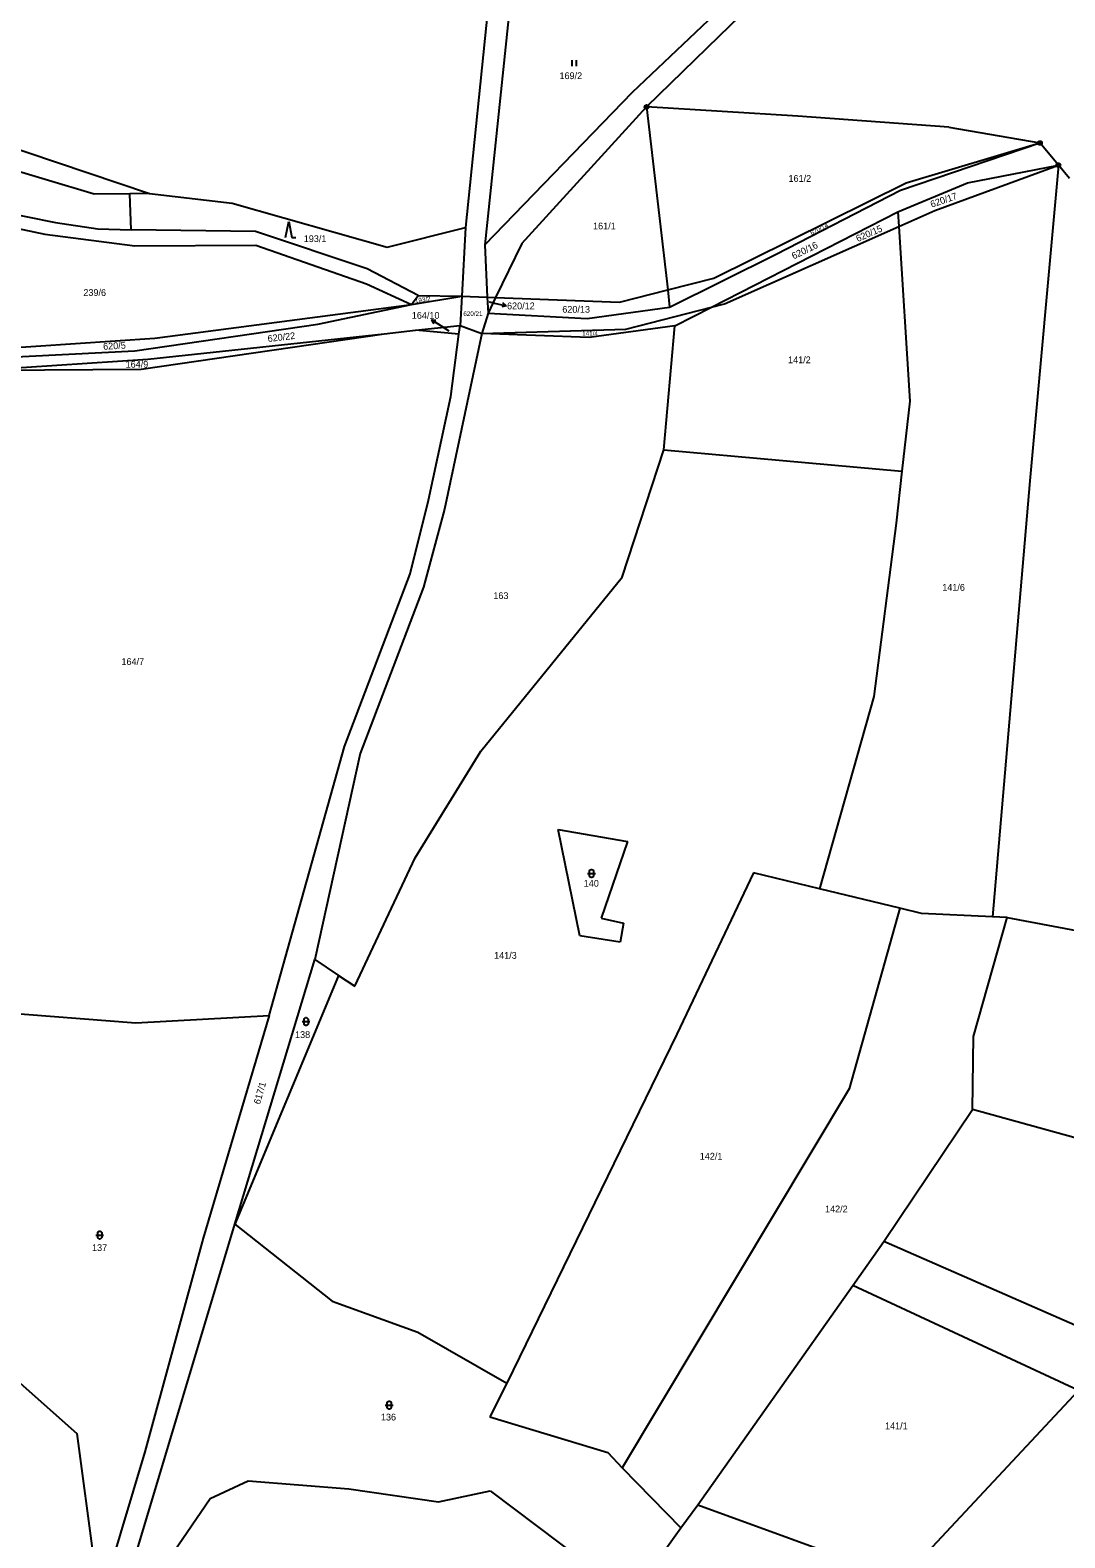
# Model space of a CAD drawing. Extents: x -794421 to -792735, y -1117671 to -1115559.
# Drawn here: x -793585 to -793325.1, y -1116417 to -1116038.2 of the extents above; entities that cross this region are included whole.
import ezdxf

# ---------------------------------------------------------------- set-up
doc = ezdxf.new("R2010")
doc.units = 0
for name, color, linetype in [('Komunikace', 7, 'Continuous'), ('Vrstva 1', 7, 'Continuous'), ('Vrstva 14', 7, 'Continuous'), ('Vrstva 16', 7, 'Continuous'), ('Vrstva 23', 7, 'Continuous'), ('Vrstva 28', 7, 'Continuous'), ('Vrstva 3', 7, 'Continuous')]:
    doc.layers.add(name, color=color, linetype=linetype)

msp = doc.modelspace()

# ---------------------------------------------------------------- linework, layer by layer
at = {"layer": 'Komunikace'}
for p, q in [((-793469.61, -1116106.43), (-793468.29, -1116106.74)), ((-793479.71, -1116113.76), (-793481.61, -1116112.55))]:
    msp.add_line(p, q, dxfattribs=at)
at = {"layer": 'Vrstva 1'}
for p, q in [((-793433.69, -1116053.72), (-793400.57, -1116022.38)), ((-793469.1, -1116023.94), (-793475.64, -1116087.76)), ((-793463.7, -1116024.71), (-793470.75, -1116092.14)), ((-793470.75, -1116092.14), (-793433.69, -1116053.72)), ((-793568.92, -1116079.35), (-793646.63, -1116056.03)), ((-793461.5, -1116091.79), (-793430.11, -1116057.44)), ((-793430.11, -1116057.44), (-793424.76, -1116103.43)), ((-793595.03, -1116065.71), (-793554.97, -1116079.2)), ((-793366.33, -1116078.39), (-793331.31, -1116066.51)), ((-793364.89, -1116076.52), (-793331.31, -1116066.51)), ((-793357.74, -1116083.48), (-793326.69, -1116072.07)), ((-793349.53, -1116076.5), (-793326.69, -1116072.07)), ((-793326.69, -1116072.07), (-793333.84, -1116151.37)), ((-793413.2, -1116100.5), (-793364.89, -1116076.52)), ((-793366.98, -1116083.8), (-793349.53, -1116076.5)), ((-793615.17, -1116079.08), (-793578.57, -1116086.49)), ((-793559.94, -1116079.27), (-793568.92, -1116079.35)), ((-793554.97, -1116079.2), (-793559.94, -1116079.27)), ((-793559.63, -1116088.36), (-793559.94, -1116079.27)), ((-793554.97, -1116079.2), (-793534.21, -1116081.67)), ((-793397.61, -1116094.45), (-793366.33, -1116078.39)), ((-793613.99, -1116082.51), (-793581.25, -1116089.41)), ((-793534.21, -1116081.67), (-793495.28, -1116092.65)), ((-793413.81, -1116107.74), (-793366.98, -1116083.8)), ((-793366.98, -1116083.8), (-793366.75, -1116087.48)), ((-793366.75, -1116087.48), (-793357.74, -1116083.48)), ((-793578.57, -1116086.49), (-793568, -1116088.05)), ((-793568, -1116088.05), (-793559.63, -1116088.36)), ((-793495.28, -1116092.65), (-793475.64, -1116087.76)), ((-793475.64, -1116087.76), (-793476.53, -1116104.96)), ((-793410.52, -1116106.9), (-793366.75, -1116087.48)), ((-793366.75, -1116087.48), (-793364.02, -1116131.35)), ((-793581.25, -1116089.41), (-793558.68, -1116092.31)), ((-793528.33, -1116088.78), (-793559.63, -1116088.36)), ((-793500.35, -1116098.15), (-793528.33, -1116088.78)), ((-793461.5, -1116091.79), (-793468.04, -1116105.33)), ((-793558.68, -1116092.31), (-793528.25, -1116092.21)), ((-793528.25, -1116092.21), (-793500.47, -1116101.91)), ((-793470.75, -1116092.14), (-793470.14, -1116105.25)), ((-793424.33, -1116107.79), (-793397.61, -1116094.45)), ((-793487.53, -1116104.85), (-793500.35, -1116098.15)), ((-793500.47, -1116101.91), (-793489.16, -1116107.13)), ((-793436.94, -1116106.52), (-793424.76, -1116103.43)), ((-793424.76, -1116103.43), (-793413.2, -1116100.5)), ((-793424.76, -1116103.43), (-793424.33, -1116107.79)), ((-793553.62, -1116115.56), (-793489.16, -1116107.13)), ((-793512.73, -1116112.02), (-793489.16, -1116107.13)), ((-793489.16, -1116107.13), (-793487.53, -1116104.85)), ((-793489.16, -1116107.13), (-793476.53, -1116104.96)), ((-793487.53, -1116104.85), (-793476.53, -1116104.96)), ((-793476.53, -1116104.96), (-793476.99, -1116112.38)), ((-793476.53, -1116104.96), (-793470.14, -1116105.25)), ((-793470.14, -1116105.25), (-793468.04, -1116105.33)), ((-793470.14, -1116105.25), (-793469.95, -1116109.28)), ((-793468.04, -1116105.33), (-793469.95, -1116109.28)), ((-793468.04, -1116105.33), (-793436.94, -1116106.52)), ((-793413.81, -1116107.74), (-793410.52, -1116106.9)), ((-793469.95, -1116109.28), (-793471.48, -1116114.35)), ((-793469.95, -1116109.28), (-793445.03, -1116110.62)), ((-793445.03, -1116110.62), (-793424.33, -1116107.79)), ((-793435.38, -1116113.28), (-793413.81, -1116107.74)), ((-793423.05, -1116112.47), (-793413.81, -1116107.74)), ((-793558.72, -1116118.73), (-793512.73, -1116112.02)), ((-793557.09, -1116123.33), (-793496.03, -1116114.43)), ((-793555.45, -1116120.83), (-793496.03, -1116114.43)), ((-793496.03, -1116114.43), (-793488.16, -1116113.58)), ((-793488.16, -1116113.58), (-793476.99, -1116112.38)), ((-793477.27, -1116114.55), (-793488.16, -1116113.58)), ((-793471.48, -1116114.35), (-793480.93, -1116158.56)), ((-793479.3, -1116130.2), (-793477.27, -1116114.55)), ((-793477.27, -1116114.55), (-793476.99, -1116112.38)), ((-793476.99, -1116112.38), (-793471.48, -1116114.35)), ((-793471.48, -1116114.35), (-793435.38, -1116113.28)), ((-793444.53, -1116115.36), (-793471.48, -1116114.35)), ((-793423.05, -1116112.47), (-793444.53, -1116115.36)), ((-793425.78, -1116143.59), (-793423.05, -1116112.47)), ((-793600.44, -1116118.71), (-793553.62, -1116115.56)), ((-793603.53, -1116120.99), (-793558.72, -1116118.73)), ((-793597.29, -1116123.63), (-793555.45, -1116120.83)), ((-793597.29, -1116123.63), (-793557.09, -1116123.33)), ((-793484.91, -1116156.22), (-793479.3, -1116130.2)), ((-793364.02, -1116131.35), (-793365.98, -1116148.93)), ((-793436.22, -1116175.62), (-793425.78, -1116143.59)), ((-793425.78, -1116143.59), (-793365.98, -1116148.93)), ((-793365.98, -1116148.93), (-793367.45, -1116162.05)), ((-793333.84, -1116151.37), (-793343.2, -1116260.98)), ((-793489.55, -1116174.74), (-793484.91, -1116156.22)), ((-793480.93, -1116158.56), (-793486.18, -1116178.14)), ((-793367.45, -1116162.05), (-793373.03, -1116205.62)), ((-793505.97, -1116218.12), (-793489.55, -1116174.74)), ((-793486.18, -1116178.14), (-793502.11, -1116219.92)), ((-793471.77, -1116219.34), (-793436.22, -1116175.62)), ((-793373.03, -1116205.62), (-793386.68, -1116253.93)), ((-793524.92, -1116285.78), (-793505.97, -1116218.12)), ((-793502.11, -1116219.92), (-793513.48, -1116271.65)), ((-793488.28, -1116246.1), (-793471.77, -1116219.34)), ((-793452.32, -1116239.04), (-793434.89, -1116242)), ((-793446.91, -1116265.75), (-793452.32, -1116239.04)), ((-793434.89, -1116242), (-793441.5, -1116261.28)), ((-793503.4, -1116278.4), (-793488.28, -1116246.1)), ((-793403.27, -1116249.91), (-793422.49, -1116290.4)), ((-793386.68, -1116253.93), (-793403.27, -1116249.91)), ((-793366.47, -1116258.82), (-793386.68, -1116253.93)), ((-793441.5, -1116261.28), (-793435.89, -1116262.54)), ((-793435.89, -1116262.54), (-793436.77, -1116267.32)), ((-793366.47, -1116258.82), (-793379.21, -1116304.19)), ((-793361.08, -1116260.12), (-793366.47, -1116258.82)), ((-793343.2, -1116260.98), (-793361.08, -1116260.12)), ((-793347.97, -1116291.05), (-793339.57, -1116261.15)), ((-793339.57, -1116261.15), (-793343.2, -1116260.98)), ((-793339.57, -1116261.15), (-793306.78, -1116267.35)), ((-793436.77, -1116267.32), (-793446.91, -1116265.75)), ((-793533.59, -1116338.16), (-793513.48, -1116271.65)), ((-793513.48, -1116271.65), (-793507.5, -1116275.68)), ((-793507.5, -1116275.68), (-793533.59, -1116338.16)), ((-793507.5, -1116275.68), (-793503.4, -1116278.4)), ((-793592.97, -1116284.93), (-793558.4, -1116287.58)), ((-793558.4, -1116287.58), (-793524.92, -1116285.78)), ((-793524.92, -1116285.78), (-793541.48, -1116341.68)), ((-793422.49, -1116290.4), (-793465.23, -1116378.1)), ((-793348.29, -1116309.37), (-793347.97, -1116291.05)), ((-793379.21, -1116304.19), (-793436.23, -1116399.41)), ((-793370.56, -1116342.5), (-793348.29, -1116309.37)), ((-793302.6, -1116322.05), (-793348.29, -1116309.37)), ((-793565.49, -1116444.67), (-793533.59, -1116338.16)), ((-793533.59, -1116338.16), (-793509.11, -1116357.56)), ((-793541.48, -1116341.68), (-793556.19, -1116395.36)), ((-793378.31, -1116353.61), (-793370.56, -1116342.5)), ((-793306.98, -1116370.42), (-793370.56, -1116342.5)), ((-793417.29, -1116408.69), (-793378.31, -1116353.61)), ((-793321.66, -1116379.99), (-793378.31, -1116353.61)), ((-793509.11, -1116357.56), (-793487.59, -1116365.35)), ((-793599.56, -1116367.45), (-793573.29, -1116390.8)), ((-793487.59, -1116365.35), (-793465.23, -1116378.1)), ((-793465.23, -1116378.1), (-793469.48, -1116386.59)), ((-793365.92, -1116427.35), (-793321.66, -1116379.99)), ((-793469.48, -1116386.59), (-793439.86, -1116395.6)), ((-793573.29, -1116390.8), (-793568.98, -1116422.79)), ((-793556.19, -1116395.36), (-793576.18, -1116462.41)), ((-793439.86, -1116395.6), (-793436.23, -1116399.41)), ((-793539.73, -1116407.1), (-793530.22, -1116402.67)), ((-793530.22, -1116402.67), (-793504.91, -1116404.65)), ((-793436.23, -1116399.41), (-793421.51, -1116414.45)), ((-793504.91, -1116404.65), (-793482.38, -1116407.93)), ((-793482.38, -1116407.93), (-793469.39, -1116405.2)), ((-793469.39, -1116405.2), (-793445.99, -1116422.87)), ((-793565.49, -1116444.67), (-793539.73, -1116407.1)), ((-793421.51, -1116414.45), (-793417.29, -1116408.69)), ((-793417.29, -1116408.69), (-793365.92, -1116427.35)), ((-793431.01, -1116427.69), (-793421.51, -1116414.45))]:
    msp.add_line(p, q, dxfattribs=at)
at = {"layer": 'Vrstva 16'}
for p, q in [((-793468.29, -1116106.74), (-793465.368, -1116107.422)), ((-793465.368, -1116107.422), (-793466.228, -1116106.707)), ((-793481.61, -1116112.55), (-793484.14, -1116110.939)), ((-793484.14, -1116110.939), (-793483.565, -1116111.897)), ((-793484.14, -1116110.939), (-793483.028, -1116111.054)), ((-793465.368, -1116107.422), (-793466.456, -1116107.681))]:
    msp.add_line(p, q, dxfattribs=at)
at = {"layer": 'Vrstva 23'}
for p, q in [((-793448.78, -1116047.23), (-793448.78, -1116045.73)), ((-793447.78, -1116045.73), (-793447.78, -1116047.23)), ((-793520.83, -1116090.24), (-793520.03, -1116086.24)), ((-793520.03, -1116086.24), (-793519.23, -1116090.24)), ((-793519.23, -1116090.24), (-793518.23, -1116090.24)), ((-793444.96, -1116250.05), (-793442.96, -1116250.05)), ((-793444.46, -1116249.45), (-793444.36, -1116249.25)), ((-793444.46, -1116250.65), (-793444.46, -1116249.45)), ((-793444.36, -1116250.85), (-793444.46, -1116250.65)), ((-793444.36, -1116249.25), (-793444.26, -1116249.15)), ((-793444.26, -1116250.95), (-793444.36, -1116250.85)), ((-793444.26, -1116249.15), (-793444.06, -1116249.05)), ((-793444.06, -1116251.05), (-793444.26, -1116250.95)), ((-793444.06, -1116249.05), (-793443.86, -1116249.05)), ((-793443.86, -1116251.05), (-793444.06, -1116251.05)), ((-793443.86, -1116249.05), (-793443.66, -1116249.15)), ((-793443.66, -1116250.95), (-793443.86, -1116251.05)), ((-793443.66, -1116249.15), (-793443.56, -1116249.25)), ((-793443.56, -1116250.85), (-793443.66, -1116250.95)), ((-793443.56, -1116249.25), (-793443.46, -1116249.45)), ((-793443.46, -1116250.65), (-793443.56, -1116250.85)), ((-793443.46, -1116249.45), (-793443.46, -1116250.65)), ((-793516.68, -1116287.29), (-793514.68, -1116287.29)), ((-793516.18, -1116286.69), (-793516.08, -1116286.49)), ((-793516.18, -1116287.89), (-793516.18, -1116286.69)), ((-793516.08, -1116288.09), (-793516.18, -1116287.89)), ((-793516.08, -1116286.49), (-793515.98, -1116286.39)), ((-793515.98, -1116288.19), (-793516.08, -1116288.09)), ((-793515.98, -1116286.39), (-793515.78, -1116286.29)), ((-793515.78, -1116288.29), (-793515.98, -1116288.19)), ((-793515.78, -1116286.29), (-793515.58, -1116286.29)), ((-793515.58, -1116288.29), (-793515.78, -1116288.29)), ((-793515.58, -1116286.29), (-793515.38, -1116286.39)), ((-793515.38, -1116288.19), (-793515.58, -1116288.29)), ((-793515.38, -1116286.39), (-793515.28, -1116286.49)), ((-793515.28, -1116288.09), (-793515.38, -1116288.19)), ((-793515.28, -1116286.49), (-793515.18, -1116286.69)), ((-793515.18, -1116287.89), (-793515.28, -1116288.09)), ((-793515.18, -1116286.69), (-793515.18, -1116287.89)), ((-793568.51, -1116340.92), (-793566.51, -1116340.92)), ((-793568.01, -1116340.32), (-793567.91, -1116340.12)), ((-793568.01, -1116341.52), (-793568.01, -1116340.32)), ((-793567.91, -1116341.72), (-793568.01, -1116341.52)), ((-793567.91, -1116340.12), (-793567.81, -1116340.02)), ((-793567.81, -1116341.82), (-793567.91, -1116341.72)), ((-793567.81, -1116340.02), (-793567.61, -1116339.92)), ((-793567.61, -1116341.92), (-793567.81, -1116341.82)), ((-793567.61, -1116339.92), (-793567.41, -1116339.92)), ((-793567.41, -1116341.92), (-793567.61, -1116341.92)), ((-793567.41, -1116339.92), (-793567.21, -1116340.02)), ((-793567.21, -1116341.82), (-793567.41, -1116341.92)), ((-793567.21, -1116340.02), (-793567.11, -1116340.12)), ((-793567.11, -1116341.72), (-793567.21, -1116341.82)), ((-793567.11, -1116340.12), (-793567.01, -1116340.32)), ((-793567.01, -1116341.52), (-793567.11, -1116341.72)), ((-793567.01, -1116340.32), (-793567.01, -1116341.52)), ((-793495.78, -1116383.65), (-793493.78, -1116383.65)), ((-793495.28, -1116383.05), (-793495.18, -1116382.85)), ((-793495.28, -1116384.25), (-793495.28, -1116383.05)), ((-793495.18, -1116382.85), (-793495.08, -1116382.75)), ((-793495.08, -1116382.75), (-793494.88, -1116382.65)), ((-793494.88, -1116382.65), (-793494.68, -1116382.65)), ((-793494.68, -1116382.65), (-793494.48, -1116382.75)), ((-793494.48, -1116382.75), (-793494.38, -1116382.85)), ((-793494.38, -1116382.85), (-793494.28, -1116383.05)), ((-793494.28, -1116383.05), (-793494.28, -1116384.25)), ((-793495.18, -1116384.45), (-793495.28, -1116384.25)), ((-793495.08, -1116384.55), (-793495.18, -1116384.45)), ((-793494.88, -1116384.65), (-793495.08, -1116384.55)), ((-793494.68, -1116384.65), (-793494.88, -1116384.65)), ((-793494.48, -1116384.55), (-793494.68, -1116384.65)), ((-793494.38, -1116384.45), (-793494.48, -1116384.55)), ((-793494.28, -1116384.25), (-793494.38, -1116384.45))]:
    msp.add_line(p, q, dxfattribs=at)
at = {"layer": 'Vrstva 28'}
for centre, radius in [((-793430.11, -1116057.44), 0.5), ((-793430.11, -1116057.44), 0.01), ((-793331.31, -1116066.51), 0.5), ((-793331.31, -1116066.51), 0.01), ((-793326.69, -1116072.07), 0.5), ((-793326.69, -1116072.07), 0.01)]:
    msp.add_circle(centre, radius, dxfattribs=at)
at = {"layer": 'Vrstva 3'}
for p, q in [((-793383.64, -1116012.24), (-793412.01, -1116039.73)), ((-793412.01, -1116039.73), (-793430.11, -1116057.44)), ((-793392.11, -1116059.8), (-793430.11, -1116057.44)), ((-793354.23, -1116062.54), (-793392.11, -1116059.8)), ((-793354.23, -1116062.54), (-793331.31, -1116066.51)), ((-793326.69, -1116072.07), (-793331.31, -1116066.51)), ((-793323.93, -1116075.39), (-793326.69, -1116072.07))]:
    msp.add_line(p, q, dxfattribs=at)

# ---------------------------------------------------------------- texts
at = {"layer": 'Vrstva 14'}
for s, height, p in [('169/2', 1.7, (-793452.003, -1116050.46)), ('161/2', 1.7, (-793394.476, -1116076.27)), ('161/1', 1.7, (-793443.57, -1116088.22)), ('193/1', 1.7, (-793516.246, -1116091.41)), ('239/6', 1.7, (-793571.61, -1116104.94)), ('620/12', 0.1, (-793469.844, -1116106.43)), ('620/21', 1.14, (-793476.157, -1116109.96)), ('620/13', 1.7, (-793451.302, -1116109.16)), ('164/10', 0.1, (-793479.931, -1116113.76)), ('141/4', 1.14, (-793446.294, -1116114.94)), ('164/9', 1.7, (-793560.999, -1116122.96)), ('141/2', 1.7, (-793394.582, -1116121.85)), ('141/6', 1.7, (-793355.852, -1116179.02)), ('163', 1.7, (-793468.62, -1116181.11)), ('164/7', 1.7, (-793562.036, -1116197.68)), ('140', 1.7, (-793445.915, -1116253.39)), ('141/3', 1.7, (-793468.432, -1116271.5)), ('138', 1.7, (-793518.43, -1116291.4)), ('142/1', 1.7, (-793416.762, -1116321.96)), ('142/2', 1.7, (-793385.299, -1116335.21)), ('137', 1.7, (-793569.427, -1116344.93)), ('136', 1.7, (-793496.86, -1116387.51)), ('141/1', 1.7, (-793370.235, -1116389.72))]:
    msp.add_text(s, height=height, dxfattribs=at).set_placement(p)
for s, height, rotation, p in [('620/17', 1.7, 19.03977, (-793358.497, -1116082.78)), ('620/14', 1.14, 26.94627, (-793388.674, -1116089.732)), ('620/15', 1.7, 23.70492, (-793377.078, -1116091.409)), ('620/16', 1.7, 25.94196, (-793393.168, -1116095.785)), ('193/2', 1.14, 7.32582, (-793488.25, -1116106.699)), ('620/22', 1.7, 6.66468, (-793525.22, -1116116.529)), ('620/5', 1.7, 3.1005, (-793566.6, -1116118.48)), ('617/1', 1.7, 73.93131, (-793527.26, -1116308.193))]:
    msp.add_text(s, height=height, rotation=rotation, dxfattribs=at).set_placement(p)
at = {"layer": 'Vrstva 16'}
for s, p in [('620/12', (-793465.18, -1116108.29)), ('164/10', (-793489.103, -1116110.68))]:
    msp.add_text(s, height=1.7, dxfattribs=at).set_placement(p)

doc.saveas('drawing.dxf')
